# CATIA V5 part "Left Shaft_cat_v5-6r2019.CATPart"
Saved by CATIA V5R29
Part number: Left hand shaft
Bounding box of the stored display mesh (mm): x 0 to 100, y -25 to 25, z -35 to 35
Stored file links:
  E:\KAVITA\RESOURCES\CATIA_RESOURCES\Tutorial Files\Tutorials\Tutorials\c16_catia_v5_6r2019_tut\c16_catia_v5_6r2019_tut\c16_catia_v5_6r2019_tut\CV joint\Left Shaft_cat_v5-6r2016.CATPart
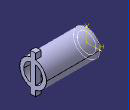
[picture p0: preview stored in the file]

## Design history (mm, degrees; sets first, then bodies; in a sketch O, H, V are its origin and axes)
Body1 (main body)
  Sketch1 on yz-plane, origin (0, 0, 0), H (0, 1, 0), V (0, 0, 1)
    circle A1 centre (0, 0) radius 25
    circle A2 centre (0, 0) radius 17.5
    radius A1 = 25
    radius A2 = 17.5
  Pad1: profile Sketch1, direction (1, 0, 0), length 100
  Sketch2 on end face of Pad1, origin (100, 0, 0), H (0, 1, 0), V (0, 0, 1)
    line L1 (-5, 35) -> (5, 35)
    line L2 (5, 35) -> (5, -35)
    line L3 (5, -35) -> (-5, -35)
    line L4 (-5, -35) -> (-5, 35)
    distance L1 L3 = 70
    distance L4 L2 = 10
    horizontal: L1 H, L3 H
    vertical: L2 V, L4 V
    symmetry: L4 L2 V, L1 L3 H
  Pad2: profile Sketch2, direction (-1, 0, 0), length 10
  Sketch3 on end face of Pad1, origin (100, 0, 0), H (0, 1, 0), V (0, 0, 1)
    line L1 (5, 35) -> (5, -35)
    line L2 (5, -35) -> (-5, -35)
    line L3 (-5, -35) -> (-5, 35)
    line L4 (-5, 35) -> (5, 35)
    length L1 = 70
    length L4 = 10
    vertical: L1 V, L3 V
    horizontal: L2 H, L4 H
    equidistance: L1 L3 O, L2 L4 O
  Pad3: profile Sketch3, direction (-1, 0, 0), length 10
Current feature: Pad2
